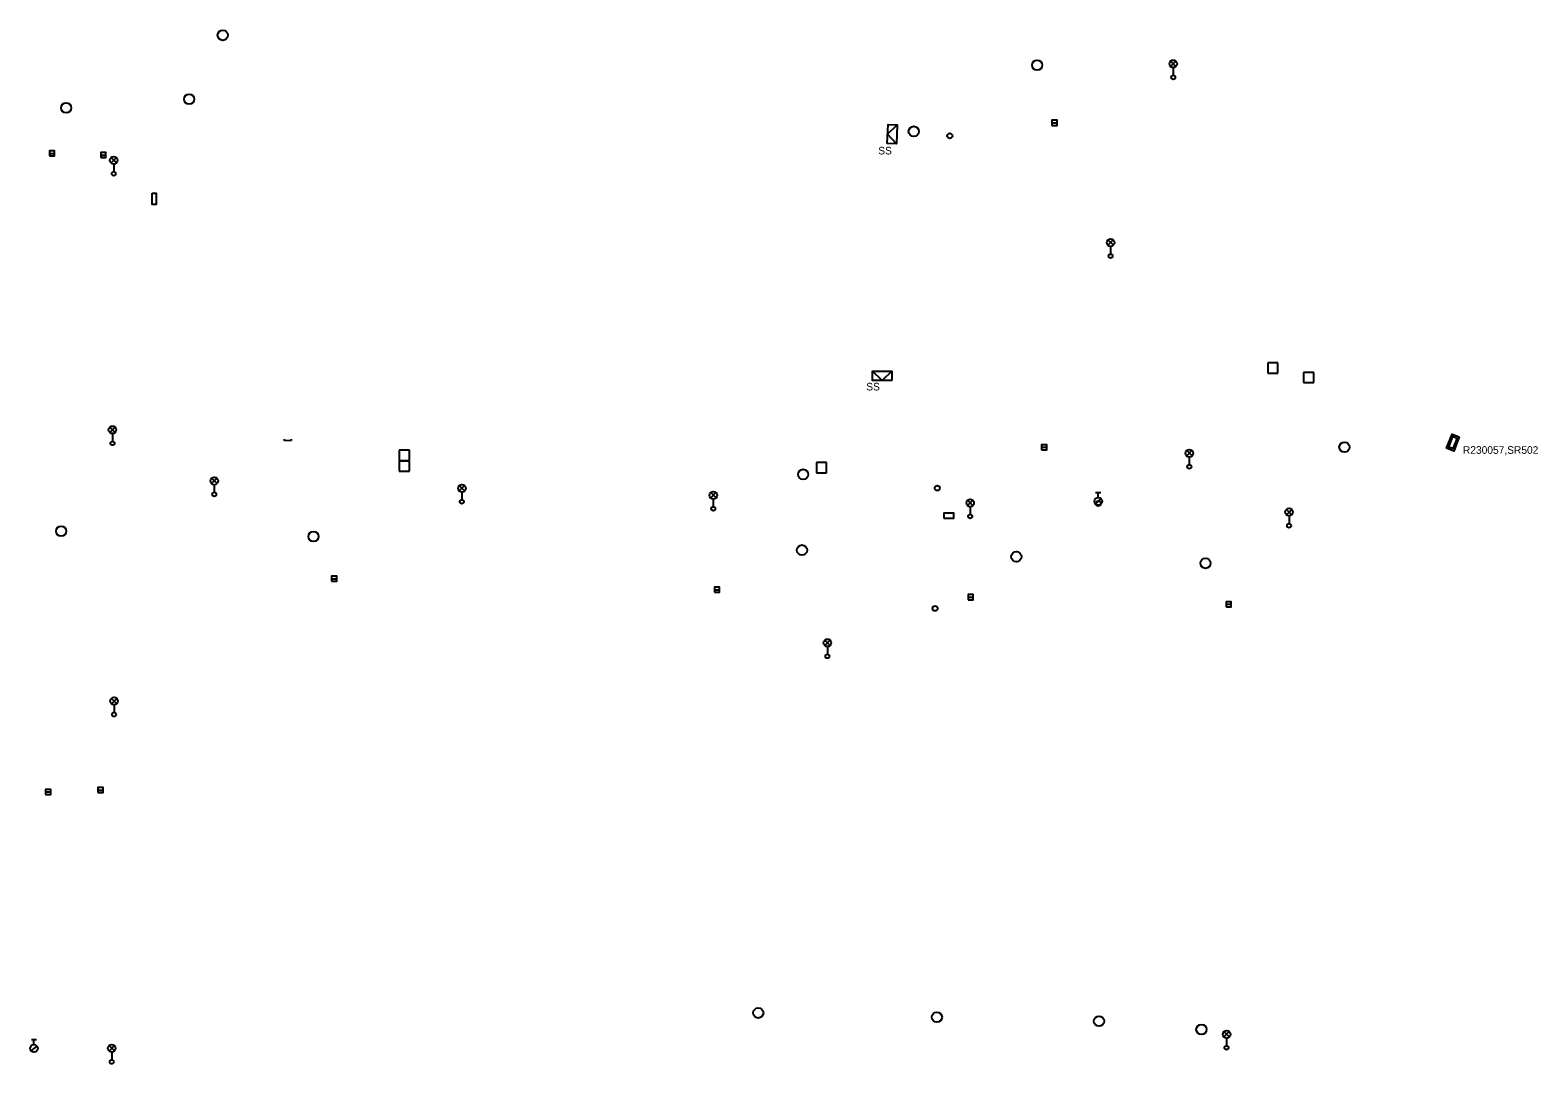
# Model space of a CAD drawing. Extents: x -584388 to -581645, y -1210859 to -1208922.
# Drawn here: x -582845.2 to -582696.9, y -1210007.4 to -1209905.7 of the extents above; entities that cross this region are included whole.
import ezdxf

# ---------------------------------------------------------------- set-up
doc = ezdxf.new("R2010")
doc.units = 0
for name, color, linetype in [('CIZÍ_NADZEM', 7, 'Continuous'), ('ELE_EON', 7, 'Continuous'), ('ELE_EON_POPIS', 7, 'Continuous')]:
    doc.layers.add(name, color=color, linetype=linetype)

msp = doc.modelspace()

# ---------------------------------------------------------------- linework, layer by layer
at = {"layer": 'CIZÍ_NADZEM'}
for p, q in [((-582733.02, -1209909.32), (-582732.5, -1209908.79)), ((-582732.49, -1209909.31), (-582733.02, -1209908.79)), ((-582732.76, -1209909.43), (-582732.76, -1209910.18)), ((-582744.69, -1209914.85), (-582744.19, -1209914.85)), ((-582843.28, -1209917.85), (-582842.78, -1209917.85)), ((-582838.23, -1209918.02), (-582837.73, -1209918.02)), ((-582837.21, -1209918.79), (-582836.69, -1209918.26)), ((-582836.68, -1209918.79), (-582837.21, -1209918.26)), ((-582836.95, -1209918.9), (-582836.95, -1209919.65)), ((-582739.18, -1209926.89), (-582738.66, -1209926.36)), ((-582738.65, -1209926.89), (-582739.18, -1209926.36)), ((-582738.92, -1209927), (-582738.92, -1209927.75)), ((-582722.47, -1209938.45), (-582723.47, -1209938.45)), ((-582723.47, -1209938.45), (-582723.47, -1209939.45)), ((-582722.47, -1209939.45), (-582722.47, -1209938.45)), ((-582718.94, -1209939.39), (-582719.94, -1209939.39)), ((-582719.94, -1209939.39), (-582719.94, -1209940.39)), ((-582718.94, -1209940.39), (-582718.94, -1209939.39)), ((-582723.47, -1209939.45), (-582722.47, -1209939.45)), ((-582719.94, -1209940.39), (-582718.94, -1209940.39)), ((-582837.34, -1209945.29), (-582836.82, -1209944.76)), ((-582836.81, -1209945.29), (-582837.34, -1209944.76)), ((-582837.08, -1209945.4), (-582837.08, -1209946.15)), ((-582745.7, -1209946.74), (-582745.2, -1209946.74)), ((-582807.87, -1209947.04), (-582808.87, -1209947.04)), ((-582808.87, -1209947.04), (-582808.87, -1209948.04)), ((-582808.87, -1209948.04), (-582807.87, -1209948.04)), ((-582807.87, -1209948.11), (-582808.87, -1209948.11)), ((-582808.87, -1209948.11), (-582808.87, -1209949.11)), ((-582807.87, -1209948.04), (-582807.87, -1209947.04)), ((-582807.87, -1209949.11), (-582807.87, -1209948.11)), ((-582766.85, -1209948.25), (-582767.85, -1209948.25)), ((-582767.85, -1209948.25), (-582767.85, -1209949.25)), ((-582766.85, -1209949.25), (-582766.85, -1209948.25)), ((-582731.44, -1209947.6), (-582730.92, -1209947.07)), ((-582730.91, -1209947.59), (-582731.44, -1209947.07)), ((-582731.18, -1209947.71), (-582731.18, -1209948.46)), ((-582827.33, -1209950.31), (-582826.81, -1209949.78)), ((-582826.8, -1209950.31), (-582827.33, -1209949.78)), ((-582808.87, -1209949.11), (-582807.87, -1209949.11)), ((-582767.85, -1209949.25), (-582766.85, -1209949.25)), ((-582827.07, -1209950.42), (-582827.07, -1209951.17)), ((-582802.98, -1209951.04), (-582802.46, -1209950.51)), ((-582802.45, -1209951.04), (-582802.98, -1209950.51)), ((-582802.72, -1209951.15), (-582802.72, -1209951.9)), ((-582778.25, -1209951.73), (-582777.73, -1209951.2)), ((-582777.72, -1209951.73), (-582778.25, -1209951.2)), ((-582740.39, -1209951.19), (-582739.89, -1209951.19)), ((-582740.14, -1209951.69), (-582740.14, -1209951.19)), ((-582777.99, -1209951.84), (-582777.99, -1209952.59)), ((-582752.99, -1209952.48), (-582752.47, -1209951.95)), ((-582752.46, -1209952.48), (-582752.99, -1209951.95)), ((-582752.73, -1209952.59), (-582752.73, -1209953.34)), ((-582740.43, -1209952.29), (-582739.84, -1209951.83)), ((-582721.63, -1209953.39), (-582721.11, -1209952.86)), ((-582721.1, -1209953.39), (-582721.63, -1209952.86)), ((-582721.37, -1209953.5), (-582721.37, -1209954.25)), ((-582815.53, -1209959.67), (-582815.03, -1209959.67)), ((-582777.88, -1209960.75), (-582777.38, -1209960.75)), ((-582752.94, -1209961.48), (-582752.44, -1209961.48)), ((-582727.55, -1209962.18), (-582727.05, -1209962.18)), ((-582767.03, -1209966.23), (-582766.51, -1209965.7)), ((-582766.5, -1209966.23), (-582767.03, -1209965.7)), ((-582766.77, -1209966.34), (-582766.77, -1209967.09)), ((-582837.18, -1209971.96), (-582836.66, -1209971.43)), ((-582836.65, -1209971.96), (-582837.18, -1209971.43)), ((-582836.92, -1209972.07), (-582836.92, -1209972.82)), ((-582843.65, -1209980.63), (-582843.15, -1209980.63)), ((-582838.51, -1209980.44), (-582838.01, -1209980.44)), ((-582727.78, -1210004.72), (-582727.26, -1210004.19)), ((-582727.25, -1210004.72), (-582727.78, -1210004.19)), ((-582845.09, -1210006.08), (-582844.5, -1210005.62)), ((-582845.05, -1210004.98), (-582844.55, -1210004.98)), ((-582844.8, -1210005.48), (-582844.8, -1210004.98)), ((-582837.41, -1210006.1), (-582836.89, -1210005.57)), ((-582836.88, -1210006.09), (-582837.41, -1210005.57)), ((-582727.52, -1210004.83), (-582727.52, -1210005.58)), ((-582837.15, -1210006.21), (-582837.15, -1210006.96))]:
    msp.add_line(p, q, dxfattribs=at)
for points in [[(-582744.69, -1209915.1), (-582744.19, -1209915.1), (-582744.19, -1209914.6), (-582744.69, -1209914.6)], [(-582843.28, -1209918.1), (-582842.78, -1209918.1), (-582842.78, -1209917.6), (-582843.28, -1209917.6)], [(-582838.23, -1209918.27), (-582837.73, -1209918.27), (-582837.73, -1209917.77), (-582838.23, -1209917.77)], [(-582745.7, -1209946.99), (-582745.2, -1209946.99), (-582745.2, -1209946.49), (-582745.7, -1209946.49)], [(-582755.33, -1209953.73), (-582754.33, -1209953.73), (-582754.33, -1209953.23), (-582755.33, -1209953.23)], [(-582815.53, -1209959.92), (-582815.03, -1209959.92), (-582815.03, -1209959.42), (-582815.53, -1209959.42)], [(-582777.88, -1209961), (-582777.38, -1209961), (-582777.38, -1209960.5), (-582777.88, -1209960.5)], [(-582752.94, -1209961.73), (-582752.44, -1209961.73), (-582752.44, -1209961.23), (-582752.94, -1209961.23)], [(-582727.55, -1209962.43), (-582727.05, -1209962.43), (-582727.05, -1209961.93), (-582727.55, -1209961.93)], [(-582843.65, -1209980.88), (-582843.15, -1209980.88), (-582843.15, -1209980.38), (-582843.65, -1209980.38)], [(-582838.51, -1209980.69), (-582838.01, -1209980.69), (-582838.01, -1209980.19), (-582838.51, -1209980.19)]]:
    msp.add_lwpolyline(points, close=True, dxfattribs=at)
for points in [[(-582833.19, -1209921.76), (-582832.79, -1209921.75), (-582832.79, -1209922.87), (-582833.19, -1209922.87), (-582833.19, -1209921.76)], [(-582820.18, -1209945.94), (-582820.18, -1209946.06), (-582819.49, -1209946.07)], [(-582819.49, -1209945.96), (-582819.49, -1209946.07)]]:
    msp.add_lwpolyline(points, dxfattribs=at)
for centre, radius in [((-582826.24, -1209906.24), 0.5), ((-582746.14, -1209909.18), 0.5), ((-582732.76, -1209909.05), 0.375), ((-582732.76, -1209910.38), 0.2), ((-582829.53, -1209912.53), 0.5), ((-582841.64, -1209913.38), 0.5), ((-582758.28, -1209915.69), 0.5), ((-582754.73, -1209916.13), 0.25), ((-582836.95, -1209918.53), 0.375), ((-582836.95, -1209919.85), 0.2), ((-582738.92, -1209926.62), 0.375), ((-582738.92, -1209927.95), 0.2), ((-582837.08, -1209945.03), 0.375), ((-582837.08, -1209946.35), 0.2), ((-582715.93, -1209946.73), 0.5), ((-582731.18, -1209947.33), 0.375), ((-582827.07, -1209950.05), 0.375), ((-582769.15, -1209949.41), 0.5), ((-582731.18, -1209948.66), 0.2), ((-582827.07, -1209951.37), 0.2), ((-582802.72, -1209950.78), 0.375), ((-582777.99, -1209951.47), 0.375), ((-582755.97, -1209950.76), 0.25), ((-582802.72, -1209952.1), 0.2), ((-582777.99, -1209952.79), 0.2), ((-582752.73, -1209952.22), 0.375), ((-582740.14, -1209952.06), 0.375), ((-582740.14, -1209952.28), 0.25), ((-582721.37, -1209953.12), 0.375), ((-582752.73, -1209953.54), 0.2), ((-582721.37, -1209954.45), 0.2), ((-582842.13, -1209955), 0.5), ((-582817.31, -1209955.51), 0.5), ((-582769.27, -1209956.85), 0.5), ((-582748.19, -1209957.5), 0.5), ((-582729.59, -1209958.15), 0.5), ((-582756.18, -1209962.59), 0.25), ((-582766.77, -1209965.97), 0.375), ((-582766.77, -1209967.29), 0.2), ((-582836.92, -1209971.7), 0.375), ((-582836.92, -1209973.02), 0.2), ((-582773.57, -1210002.36), 0.5), ((-582756, -1210002.77), 0.5), ((-582740.06, -1210003.17), 0.5), ((-582729.99, -1210003.99), 0.5), ((-582727.52, -1210004.46), 0.375), ((-582844.8, -1210005.85), 0.375), ((-582837.15, -1210005.83), 0.375), ((-582727.52, -1210005.78), 0.2), ((-582837.15, -1210007.16), 0.2)]:
    msp.add_circle(centre, radius, dxfattribs=at)
at = {"layer": 'ELE_EON'}
for points in [[(-582760.89, -1209916.88), (-582760.81, -1209915.01), (-582759.91, -1209915.04), (-582759.99, -1209916.92)], [(-582760.44, -1209940.17), (-582762.32, -1209940.17), (-582762.32, -1209939.27), (-582760.44, -1209939.27)], [(-582704.64, -1209945.72), (-582705.18, -1209947.12), (-582705.88, -1209946.85), (-582705.34, -1209945.45)], [(-582704.85, -1209945.85), (-582705.25, -1209946.88), (-582705.67, -1209946.72), (-582705.27, -1209945.69)]]:
    msp.add_lwpolyline(points, close=True, dxfattribs=at)
for points in [[(-582759.99, -1209916.92), (-582760.85, -1209915.95), (-582759.91, -1209915.04)], [(-582760.44, -1209939.27), (-582761.38, -1209940.17), (-582762.32, -1209939.27)]]:
    msp.add_lwpolyline(points, dxfattribs=at)

# ---------------------------------------------------------------- texts
at = {"layer": 'ELE_EON_POPIS'}
for s, p in [('SS', (-582761.77, -1209917.96)), ('SS', (-582762.95, -1209941.16)), ('R230057,SR502', (-582704.27, -1209947.39))]:
    msp.add_text(s, height=0.75, dxfattribs=at).set_placement(p)

doc.saveas('drawing.dxf')
